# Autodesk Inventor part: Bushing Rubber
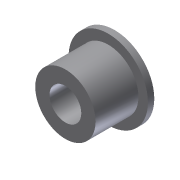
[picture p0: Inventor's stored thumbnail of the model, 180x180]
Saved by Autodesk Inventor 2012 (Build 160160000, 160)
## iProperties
Created: 2010-03
Part Number: Bushing Rubber
Document SubType Name: Modeling
Designer: bhakira
Density: 1 g/cm^3
Material: Default
Author: bhakira
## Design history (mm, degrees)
sketch "Sketch1"
  geometry: L1 (25, 31)-(25, 27); L2 (25, 27)-(19, 27); L3 (19, 27)-(19, 0); L4 (19, 0)-(0, 0); L5 (0, 0)-(0, 31); L6 (0, 31)-(25, 31); 1 further point
  constraints: 12 end point, 1 coincident, 1 other
  dimensions: "d1" = 50 diameter of L1 L5; "d2" = 38 diameter of L3 L5; "d3" = 4 distance of L1.start L1.end; "d4" = 27 distance between parallel lines of L4 L2
revolve "Revolution1" sketch "Sketch1" stored, may be unused: angle "d5" = 90 deg
hole "Hole1" diameter "d8" = 20; stored, may be unused: countersink angle "d12" = 82 deg, drill point angle "d14" = 118 deg; dims "d6" = 10, "d7" = 10, "d9" = 6, "d10" = 34.925, "d11" = 2, "d13" = 8
body "Solid1"
